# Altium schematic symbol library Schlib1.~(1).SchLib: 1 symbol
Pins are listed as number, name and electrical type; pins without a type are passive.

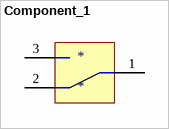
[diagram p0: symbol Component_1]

## Component_1
designator *
pins: 1 in, 2, 3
